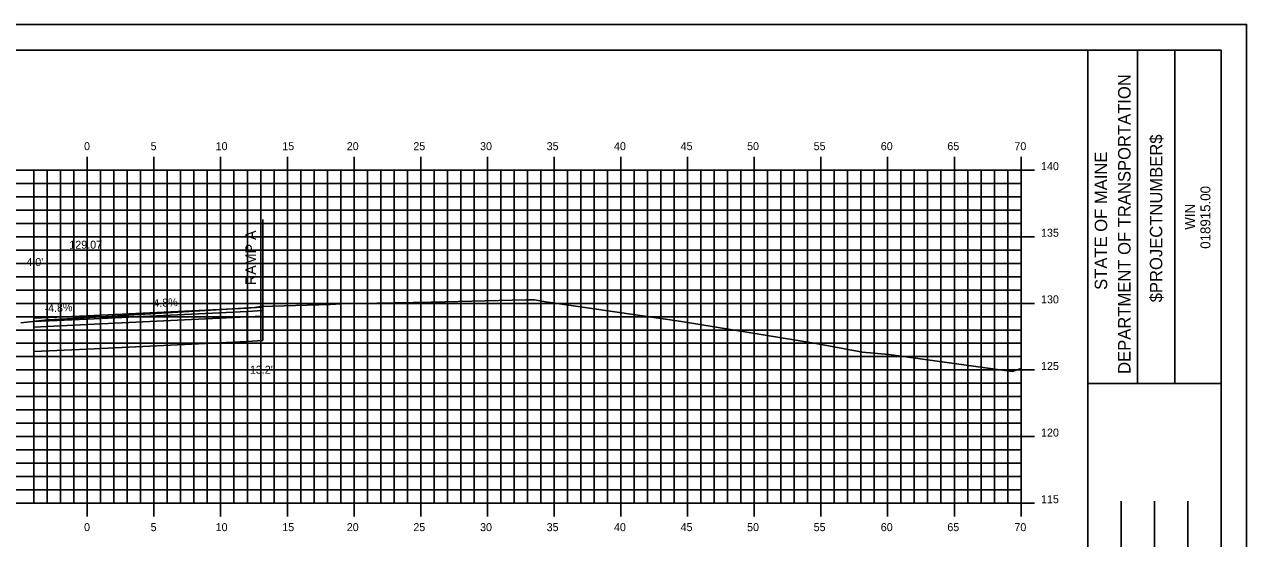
# Model space of a CAD drawing. Extents: x 851073 to 851245, y 365624 to 365734.
# Drawn here: x 851151.5 to 851243.2, y 365695.4 to 365734 of the extents above; entities that cross this region are included whole.
import ezdxf

# ---------------------------------------------------------------- set-up
doc = ezdxf.new("R2010")
doc.units = 0
for name, color, linetype in [('ANNOTATION', 7, 'Continuous'), ('BORDER', 7, 'Continuous'), ('D_Roadway_Centerline', 7, 'Continuous'), ('D_Roadway_Centerline_Text', 7, 'Continuous'), ('D_Roadway_Edge_Shoulder', 7, 'Continuous'), ('D_Roadway_Pavement', 7, 'Continuous'), ('D_Roadway_SubGrade', 7, 'Continuous'), ('D_Text_Standard', 7, 'Continuous'), ('H_V ANNOTATION', 7, 'Continuous'), ('M_Roadway_Centerline', 7, 'Continuous'), ('MAJOR', 7, 'Continuous'), ('MINOR', 7, 'Continuous'), ('PLOT BOUNDARY', 7, 'Continuous'), ('S_Roadway_Centerline', 7, 'Continuous')]:
    doc.layers.add(name, color=color, linetype=linetype)

msp = doc.modelspace()

# ---------------------------------------------------------------- linework, layer by layer
at = {"layer": 'BORDER'}
for p, q in [((851231.253, 365627.027), (851231.253, 365732.027)), ((851234.981, 365707.024), (851234.981, 365732.024)), ((851237.776, 365707.024), (851237.776, 365732.024)), ((851231.254, 365707.021), (851241.253, 365707.021)), ((851233.753, 365689.53), (851233.753, 365698.177)), ((851236.253, 365689.53), (851236.253, 365698.177)), ((851238.753, 365689.53), (851238.753, 365698.177))]:
    msp.add_line(p, q, dxfattribs=at)
msp.add_lwpolyline([(851081.253, 365627.027), (851241.253, 365627.027), (851241.253, 365732.027), (851081.253, 365732.027)], close=True, dxfattribs=at)
at = {"layer": 'D_Roadway_Centerline'}
msp.add_lwpolyline([(851152.252, 365711.905), (851156.252, 365712.097), (851156.253, 365712.097), (851156.256, 365712.097), (851168.253, 365712.673), (851168.55, 365712.687), (851169.417, 365712.729)], dxfattribs=at)
at = {"layer": 'D_Roadway_Edge_Shoulder'}
for p, q in [((851168.253, 365712.673), (851168.253, 365712.423)), ((851156.253, 365712.097), (851156.253, 365711.847))]:
    msp.add_line(p, q, dxfattribs=at)
at = {"layer": 'D_Roadway_Pavement'}
for points in [[(851156.251, 365711.847), (851168.251, 365712.423), (851168.251, 365712.006), (851156.251, 365711.43)], [(851156.251, 365711.847), (851152.251, 365711.655), (851152.251, 365711.238), (851156.251, 365711.43)]]:
    msp.add_lwpolyline(points, close=True, dxfattribs=at)
msp.add_lwpolyline([(851169.412, 365712.062), (851168.251, 365712.006), (851168.251, 365712.423), (851169.412, 365712.479)], dxfattribs=at)
at = {"layer": 'D_Roadway_SubGrade'}
for p, q in [((851169.412, 365719.316), (851169.412, 365712.569)), ((851169.412, 365712.569), (851169.412, 365710.229))]:
    msp.add_line(p, q, dxfattribs=at)
for points in [[(851156.251, 365711.43), (851152.251, 365711.238), (851152.251, 365711.738), (851152.251, 365711.905), (851152.251, 365709.405), (851156.251, 365709.597)], [(851156.251, 365711.43), (851168.251, 365712.006), (851168.251, 365710.173), (851156.251, 365709.597)]]:
    msp.add_lwpolyline(points, close=True, dxfattribs=at)
msp.add_lwpolyline([(851169.412, 365710.229), (851168.251, 365710.173), (851168.251, 365712.006), (851169.412, 365712.062)], dxfattribs=at)
at = {"layer": 'MAJOR'}
for p, q in [((851156.253, 365724.029), (851156.253, 365723.027)), ((851161.253, 365724.029), (851161.253, 365723.027)), ((851166.253, 365724.029), (851166.253, 365723.027)), ((851171.253, 365724.029), (851171.253, 365723.027)), ((851176.253, 365724.029), (851176.253, 365723.027)), ((851181.253, 365724.029), (851181.253, 365723.027)), ((851186.253, 365724.029), (851186.253, 365723.027)), ((851191.253, 365724.029), (851191.253, 365723.027)), ((851196.253, 365724.029), (851196.253, 365723.027)), ((851201.253, 365724.029), (851201.253, 365723.027)), ((851206.253, 365724.029), (851206.253, 365723.027)), ((851211.253, 365724.029), (851211.253, 365723.027)), ((851216.253, 365724.029), (851216.253, 365723.027)), ((851221.253, 365724.029), (851221.253, 365723.027)), ((851226.253, 365724.029), (851226.253, 365723.027)), ((851086.253, 365723.027), (851226.253, 365723.027)), ((851086.253, 365723.027), (851226.253, 365723.027)), ((851156.253, 365698.027), (851156.253, 365723.027)), ((851161.253, 365698.027), (851161.253, 365723.027)), ((851166.253, 365698.027), (851166.253, 365723.027)), ((851171.253, 365698.027), (851171.253, 365723.027)), ((851176.253, 365698.027), (851176.253, 365723.027)), ((851181.253, 365698.027), (851181.253, 365723.027)), ((851186.253, 365698.027), (851186.253, 365723.027)), ((851191.253, 365698.027), (851191.253, 365723.027)), ((851196.253, 365698.027), (851196.253, 365723.027)), ((851201.253, 365698.027), (851201.253, 365723.027)), ((851206.253, 365698.027), (851206.253, 365723.027)), ((851211.253, 365698.027), (851211.253, 365723.027)), ((851216.253, 365698.027), (851216.253, 365723.027)), ((851221.253, 365698.027), (851221.253, 365723.027)), ((851227.255, 365723.027), (851225.251, 365723.027)), ((851226.253, 365698.027), (851226.253, 365723.027)), ((851226.253, 365698.027), (851226.253, 365723.027)), ((851086.253, 365718.027), (851226.253, 365718.027)), ((851227.255, 365718.027), (851225.251, 365718.027)), ((851086.253, 365713.027), (851226.253, 365713.027)), ((851227.255, 365713.027), (851225.251, 365713.027)), ((851086.253, 365708.027), (851226.253, 365708.027)), ((851227.255, 365708.027), (851225.251, 365708.027)), ((851086.253, 365703.027), (851226.253, 365703.027)), ((851227.255, 365703.027), (851225.251, 365703.027)), ((851086.253, 365698.027), (851226.253, 365698.027)), ((851086.253, 365698.027), (851226.253, 365698.027)), ((851156.253, 365697.025), (851156.253, 365698.027)), ((851161.253, 365697.025), (851161.253, 365698.027)), ((851166.253, 365697.025), (851166.253, 365698.027)), ((851171.253, 365697.025), (851171.253, 365698.027)), ((851176.253, 365697.025), (851176.253, 365698.027)), ((851181.253, 365697.025), (851181.253, 365698.027)), ((851186.253, 365697.025), (851186.253, 365698.027)), ((851191.253, 365697.025), (851191.253, 365698.027)), ((851196.253, 365697.025), (851196.253, 365698.027)), ((851201.253, 365697.025), (851201.253, 365698.027)), ((851206.253, 365697.025), (851206.253, 365698.027)), ((851211.253, 365697.025), (851211.253, 365698.027)), ((851216.253, 365697.025), (851216.253, 365698.027)), ((851221.253, 365697.025), (851221.253, 365698.027)), ((851227.255, 365698.027), (851225.251, 365698.027)), ((851226.253, 365697.025), (851226.253, 365698.027))]:
    msp.add_line(p, q, dxfattribs=at)
at = {"layer": 'MINOR'}
for p, q in [((851152.253, 365698.027), (851152.253, 365723.027)), ((851153.253, 365698.027), (851153.253, 365723.027)), ((851154.253, 365698.027), (851154.253, 365723.027)), ((851155.253, 365698.027), (851155.253, 365723.027)), ((851157.253, 365698.027), (851157.253, 365723.027)), ((851158.253, 365698.027), (851158.253, 365723.027)), ((851159.253, 365698.027), (851159.253, 365723.027)), ((851160.253, 365698.027), (851160.253, 365723.027)), ((851162.253, 365698.027), (851162.253, 365723.027)), ((851163.253, 365698.027), (851163.253, 365723.027)), ((851164.253, 365698.027), (851164.253, 365723.027)), ((851165.253, 365698.027), (851165.253, 365723.027)), ((851167.253, 365698.027), (851167.253, 365723.027)), ((851168.253, 365698.027), (851168.253, 365723.027)), ((851169.253, 365698.027), (851169.253, 365723.027)), ((851170.253, 365698.027), (851170.253, 365723.027)), ((851172.253, 365698.027), (851172.253, 365723.027)), ((851173.253, 365698.027), (851173.253, 365723.027)), ((851174.253, 365698.027), (851174.253, 365723.027)), ((851175.253, 365698.027), (851175.253, 365723.027)), ((851177.253, 365698.027), (851177.253, 365723.027)), ((851178.253, 365698.027), (851178.253, 365723.027)), ((851179.253, 365698.027), (851179.253, 365723.027)), ((851180.253, 365698.027), (851180.253, 365723.027)), ((851182.253, 365698.027), (851182.253, 365723.027)), ((851183.253, 365698.027), (851183.253, 365723.027)), ((851184.253, 365698.027), (851184.253, 365723.027)), ((851185.253, 365698.027), (851185.253, 365723.027)), ((851187.253, 365698.027), (851187.253, 365723.027)), ((851188.253, 365698.027), (851188.253, 365723.027)), ((851189.253, 365698.027), (851189.253, 365723.027)), ((851190.253, 365698.027), (851190.253, 365723.027)), ((851192.253, 365698.027), (851192.253, 365723.027)), ((851193.253, 365698.027), (851193.253, 365723.027)), ((851194.253, 365698.027), (851194.253, 365723.027)), ((851195.253, 365698.027), (851195.253, 365723.027)), ((851197.253, 365698.027), (851197.253, 365723.027)), ((851198.253, 365698.027), (851198.253, 365723.027)), ((851199.253, 365698.027), (851199.253, 365723.027)), ((851200.253, 365698.027), (851200.253, 365723.027)), ((851202.253, 365698.027), (851202.253, 365723.027)), ((851203.253, 365698.027), (851203.253, 365723.027)), ((851204.253, 365698.027), (851204.253, 365723.027)), ((851205.253, 365698.027), (851205.253, 365723.027)), ((851207.253, 365698.027), (851207.253, 365723.027)), ((851208.253, 365698.027), (851208.253, 365723.027)), ((851209.253, 365698.027), (851209.253, 365723.027)), ((851210.253, 365698.027), (851210.253, 365723.027)), ((851212.253, 365698.027), (851212.253, 365723.027)), ((851213.253, 365698.027), (851213.253, 365723.027)), ((851214.253, 365698.027), (851214.253, 365723.027)), ((851215.253, 365698.027), (851215.253, 365723.027)), ((851217.253, 365698.027), (851217.253, 365723.027)), ((851218.253, 365698.027), (851218.253, 365723.027)), ((851219.253, 365698.027), (851219.253, 365723.027)), ((851220.253, 365698.027), (851220.253, 365723.027)), ((851222.253, 365698.027), (851222.253, 365723.027)), ((851223.253, 365698.027), (851223.253, 365723.027)), ((851224.253, 365698.027), (851224.253, 365723.027)), ((851225.253, 365698.027), (851225.253, 365723.027)), ((851086.253, 365722.027), (851226.253, 365722.027)), ((851226.253, 365722.027), (851225.251, 365722.027)), ((851086.253, 365721.027), (851226.253, 365721.027)), ((851226.253, 365721.027), (851225.251, 365721.027)), ((851086.253, 365720.027), (851226.253, 365720.027)), ((851226.253, 365720.027), (851225.251, 365720.027)), ((851086.253, 365719.027), (851226.253, 365719.027)), ((851226.253, 365719.027), (851225.251, 365719.027)), ((851086.253, 365717.027), (851226.253, 365717.027)), ((851226.253, 365717.027), (851225.251, 365717.027)), ((851086.253, 365716.027), (851226.253, 365716.027)), ((851226.253, 365716.027), (851225.251, 365716.027)), ((851086.253, 365715.027), (851226.253, 365715.027)), ((851226.253, 365715.027), (851225.251, 365715.027)), ((851086.253, 365714.027), (851226.253, 365714.027)), ((851226.253, 365714.027), (851225.251, 365714.027)), ((851086.253, 365712.027), (851226.253, 365712.027)), ((851226.253, 365712.027), (851225.251, 365712.027)), ((851086.253, 365711.027), (851226.253, 365711.027)), ((851226.253, 365711.027), (851225.251, 365711.027)), ((851086.253, 365710.027), (851226.253, 365710.027)), ((851226.253, 365710.027), (851225.251, 365710.027)), ((851086.253, 365709.027), (851226.253, 365709.027)), ((851226.253, 365709.027), (851225.251, 365709.027)), ((851086.253, 365707.027), (851226.253, 365707.027)), ((851226.253, 365707.027), (851225.251, 365707.027)), ((851086.253, 365706.027), (851226.253, 365706.027)), ((851226.253, 365706.027), (851225.251, 365706.027)), ((851086.253, 365705.027), (851226.253, 365705.027)), ((851226.253, 365705.027), (851225.251, 365705.027)), ((851086.253, 365704.027), (851226.253, 365704.027)), ((851226.253, 365704.027), (851225.251, 365704.027)), ((851086.253, 365702.027), (851226.253, 365702.027)), ((851226.253, 365702.027), (851225.251, 365702.027)), ((851086.253, 365701.027), (851226.253, 365701.027)), ((851226.253, 365701.027), (851225.251, 365701.027)), ((851086.253, 365700.027), (851226.253, 365700.027)), ((851226.253, 365700.027), (851225.251, 365700.027)), ((851086.253, 365699.027), (851226.253, 365699.027)), ((851226.253, 365699.027), (851225.251, 365699.027))]:
    msp.add_line(p, q, dxfattribs=at)
at = {"layer": 'PLOT BOUNDARY'}
msp.add_lwpolyline([(851073.159, 365623.968), (851243.159, 365623.968), (851243.159, 365733.968), (851073.159, 365733.968)], close=True, dxfattribs=at)
at = {"layer": 'S_Roadway_Centerline'}
msp.add_lwpolyline([(851151.273, 365711.565), (851153.26, 365711.799), (851155.225, 365711.902), (851162.635, 365712.335), (851168.785, 365712.723), (851169.263, 365712.8), (851174.475, 365712.954), (851175.262, 365712.986), (851182.022, 365713.115), (851189.121, 365713.282), (851189.747, 365713.281), (851190.63, 365713.151), (851200.811, 365711.666), (851210.744, 365710.035), (851214.378, 365709.366), (851216.342, 365709.181), (851225.581, 365707.914), (851226.253, 365708.147)], dxfattribs=at)

# ---------------------------------------------------------------- texts
at = {"layer": 'ANNOTATION'}
for s, height, rotation, p in [('RAMP A', 0.8, 90, (851168.905, 365714.4)), ('-4.8%', 0.6, 2.74798, (851153.06, 365712.345)), ('4.8%', 0.6, 2.74801, (851161.223, 365712.737))]:
    msp.add_text(s, height=height, rotation=rotation, dxfattribs=at).set_placement(p)
at = {"layer": 'BORDER'}
for s, height, p in [('DEPARTMENT OF TRANSPORTATION', 0.93176, (851234.46, 365707.733)), ('$PROJECTNUMBER$', 0.93176, (851236.845, 365713.106)), ('STATE OF MAINE', 0.93176, (851232.708, 365714.039)), ('018915.00', 0.7453, (851240.448, 365717.125)), ('WIN', 0.7453, (851239.29, 365718.557))]:
    msp.add_text(s, height=height, rotation=90, dxfattribs=at).set_placement(p)
at = {"layer": 'D_Roadway_Centerline'}
for s, p in [('C', (851156.247, 365712.097)), ('L', (851156.253, 365712.089))]:
    msp.add_text(s, height=0.0146, dxfattribs=at).set_placement(p)
at = {"layer": 'D_Roadway_Centerline_Text'}
msp.add_text('129.07', height=0.6, dxfattribs=at).set_placement((851154.91, 365717.129))
at = {"layer": 'D_Text_Standard'}
for s, p in [("4.0'", (851151.689, 365715.826)), ("13.2'", (851168.446, 365707.744))]:
    msp.add_text(s, height=0.6, dxfattribs=at).set_placement(p)
at = {"layer": 'H_V ANNOTATION'}
for s, p in [('0', (851156.012, 365724.527)), ('5', (851161.004, 365724.527)), ('10', (851165.878, 365724.527)), ('15', (851170.87, 365724.527)), ('20', (851175.707, 365724.527)), ('25', (851180.699, 365724.527)), ('30', (851185.701, 365724.527)), ('35', (851190.693, 365724.527)), ('40', (851195.739, 365724.527)), ('45', (851200.731, 365724.527)), ('50', (851205.717, 365724.527)), ('55', (851210.709, 365724.527)), ('60', (851215.739, 365724.527)), ('65', (851220.731, 365724.527)), ('70', (851225.755, 365724.527)), ('140', (851227.753, 365723.027)), ('135', (851227.753, 365718.027)), ('130', (851227.753, 365713.027)), ('125', (851227.753, 365708.027)), ('120', (851227.753, 365703.027)), ('115', (851227.753, 365698.027)), ('0', (851156.012, 365695.927)), ('5', (851161.004, 365695.927)), ('10', (851165.878, 365695.927)), ('15', (851170.87, 365695.927)), ('20', (851175.707, 365695.927)), ('25', (851180.699, 365695.927)), ('30', (851185.701, 365695.927)), ('35', (851190.693, 365695.927)), ('40', (851195.739, 365695.927)), ('45', (851200.731, 365695.927)), ('50', (851205.717, 365695.927)), ('55', (851210.709, 365695.927)), ('60', (851215.739, 365695.927)), ('65', (851220.731, 365695.927)), ('70', (851225.755, 365695.927))]:
    msp.add_text(s, height=0.6, dxfattribs=at).set_placement(p)
at = {"layer": 'M_Roadway_Centerline'}
for s, p in [('C', (851169.258, 365712.8)), ('L', (851169.263, 365712.793))]:
    msp.add_text(s, height=0.0146, dxfattribs=at).set_placement(p)

doc.saveas('drawing.dxf')
